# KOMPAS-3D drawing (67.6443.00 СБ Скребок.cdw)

Referenced files in C:\Documents and Settings\kobozev_in\Рабочий стол\Чертежи\Чертежи\ППО КО 2005\Я-3\Скребки\67.6443.00 Скребок НКТ 73\: 67.6443.00 Спецификация.spw
Referenced files: Скребок СБ.cdw
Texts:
  Скребок для чистки труб НКТ73 (2 1/2")
  ПТ-2
  *Размеры для справок.
  Паять, припой - ПМЦ 54 ГОСТ 23137-78, латунь Л 62, Л 63
  ГОСТ 15527-83.
  При сборке скребки (дет. поз. 3) распологать соосно.
  Маркировать шрифтом №5 глубиной 0,3...0,5:
  - предприятие-изготовитель;
  - месяц и год изготовления.
  При сборке обеспечить свободное движение планки (дет. поз. 2) и
  свободное вращение  вертлюга (дет. поз. 5) и пальца (дет. поз. 6) на
  своих осях.
  Размер 46 +2  при необходимости достигнуть подгибанием
  скребка..
  Планка
  Скребок
  Скоба
  Вертлюг
  Палец
  Ось
  Втулка
  Заклепка В 5х16.02
  Заклепка
  Заклепка В 5х22.02
  ГОСТ 10299-80
  для чистки труб
  НКТ73 (2 1/2")
  Нач. КО
Dimensions and other numbers on the sheet: 415; 5; 12; 56; 4 места; 6,3; 1; 2; 3; 4; 8; 9; 7; 6; 10; 67.6443.01; 67.6443.02; 67.6443.03; 67.6443.04; 67.6443.05; 67.6443.06; 67.6443.07; 67.6443.08; 1:1; 0,7; 0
